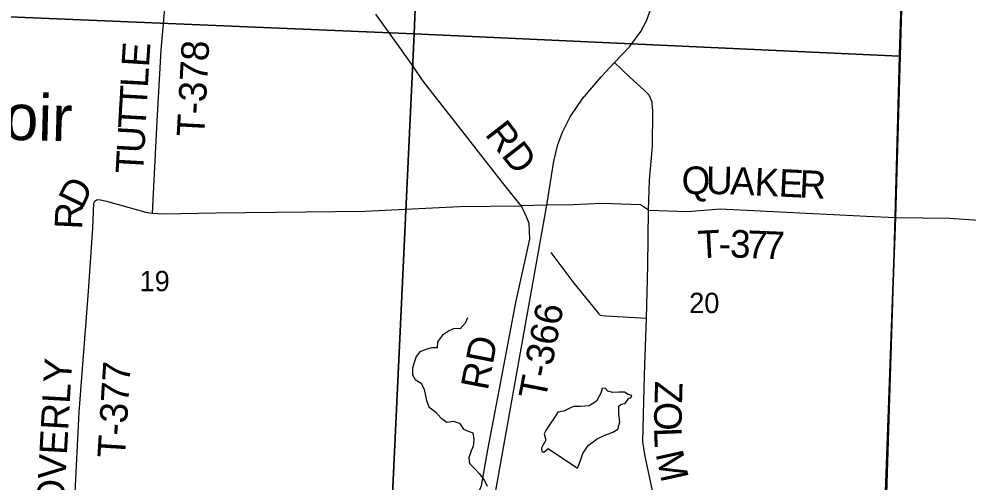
# Model space of a CAD drawing. Extents: x 1759416 to 2214760, y 252598 to 1116833.
# Drawn here: x 1948045 to 1958374, y 912773 to 917809 of the extents above; entities that cross this region are included whole.
import ezdxf

# ---------------------------------------------------------------- set-up
doc = ezdxf.new("R2010")
doc.units = 0
for name, color, linetype in [('GM_X_County_Road', 7, 'Continuous'), ('GM_X_County_Road_Text', 7, 'Continuous'), ('GM_X_Major_Lake_Text', 7, 'Continuous'), ('GM_X_Minor_Lake', 7, 'Continuous'), ('GM_X_Minor_River', 7, 'Continuous'), ('GM_X_Section', 7, 'Continuous'), ('GM_X_Section_Text', 7, 'Continuous'), ('GM_X_State_Route', 7, 'Continuous'), ('GM_X_Township', 7, 'Continuous'), ('GM_X_Township_Road', 7, 'Continuous'), ('GM_X_Township_Road_Text', 7, 'Continuous')]:
    doc.layers.add(name, color=color, linetype=linetype)

msp = doc.modelspace()

# ---------------------------------------------------------------- linework, layer by layer
at = {"layer": 'GM_X_County_Road'}
for points in [[(1953509, 915776), (1953318, 916014), (1952930, 916513), (1952445, 917134), (1952337, 917290), (1952198, 917489), (1951929, 917861)], [(1954937, 916894), (1954936, 916904), (1954903, 916980), (1954849, 917034), (1954695, 917171), (1954528, 917336)], [(1954978, 912496), (1954877, 912965), (1954855, 913071), (1954834, 913209), (1954852, 913937), (1954873, 914556), (1954889, 915125), (1954897, 915731), (1954907, 916057), (1954940, 916425), (1954944, 916807), (1954937, 916894)], [(1954897, 915731), (1954811, 915786), (1954390, 915801), (1954075, 915786), (1953791, 915785)], [(1953791, 915785), (1953509, 915776)]]:
    msp.add_lwpolyline(points, dxfattribs=at)
at = {"layer": 'GM_X_Minor_Lake'}
for points in [[(1954125, 912925), (1954151, 912995), (1954183, 913083), (1954241, 913170), (1954337, 913244), (1954415, 913278), (1954507, 913316), (1954561, 913346), (1954584, 913428), (1954574, 913512), (1954572, 913599), (1954598, 913619), (1954642, 913625), (1954684, 913683), (1954704, 913687), (1954716, 913715), (1954676, 913725), (1954636, 913749), (1954574, 913751), (1954508, 913747), (1954454, 913761), (1954424, 913793), (1954391, 913789), (1954377, 913739), (1954329, 913651), (1954249, 913601), (1954155, 913593), (1954079, 913595), (1954031, 913571), (1953975, 913545), (1953911, 913533), (1953873, 913476), (1953818, 913394), (1953778, 913332), (1953760, 913296), (1953780, 913228), (1953750, 913178), (1953730, 913140), (1953734, 913103), (1953758, 913099), (1953804, 913136)], [(1953804, 913136), (1954125, 912925)]]:
    msp.add_lwpolyline(points, dxfattribs=at)
at = {"layer": 'GM_X_Minor_River'}
msp.add_lwpolyline([(1952926, 914560), (1952900, 914501), (1952846, 914439), (1952782, 914441), (1952720, 914415), (1952653, 914369), (1952601, 914297), (1952597, 914233), (1952533, 914233), (1952471, 914213), (1952407, 914187), (1952369, 914137), (1952345, 914074), (1952329, 914010), (1952329, 913940), (1952357, 913888), (1952423, 913848), (1952453, 913778), (1952469, 913711), (1952479, 913659), (1952507, 913589), (1952577, 913537), (1952637, 913471), (1952703, 913424), (1952773, 913435), (1952839, 913414), (1952883, 913348), (1952933, 913324), (1952983, 913308), (1952997, 913236), (1952987, 913164), (1952965, 913112), (1952939, 913035), (1952949, 912973), (1953007, 912915), (1953055, 912865), (1953111, 912789), (1953141, 912728)], dxfattribs=at)
at = {"layer": 'GM_X_Section'}
for points in [[(1947099, 921072), (1952477, 920886), (1952344, 917647), (1946987, 917871)], [(1952477, 920886), (1953394, 920844), (1955546, 920745), (1957728, 920644), (1957626, 917421), (1957626, 917405), (1952344, 917647)], [(1952344, 917647), (1952087, 912177), (1946673, 912411), (1946987, 917871)], [(1952344, 917647), (1957626, 917405), (1957552, 914730), (1957469, 912061), (1957464, 911948), (1952087, 912177)]]:
    msp.add_lwpolyline(points, close=True, dxfattribs=at)
at = {"layer": 'GM_X_State_Route'}
for points in [[(1954198, 916965), (1954380, 917178), (1954528, 917336), (1954688, 917507), (1954814, 917674), (1954879, 917797), (1954965, 918053), (1955223, 919187)], [(1952216, 906771), (1952343, 907503), (1952586, 908815), (1952810, 910268), (1952866, 910610), (1953791, 915785), (1953865, 916262), (1953910, 916442), (1953960, 916579), (1954042, 916745), (1954128, 916868), (1954194, 916961), (1954198, 916965)]]:
    msp.add_lwpolyline(points, dxfattribs=at)
at = {"layer": 'GM_X_Township'}
for points in [[(1959158, 906479), (1957243, 906546), (1957347, 909188), (1957585, 915650), (1957760, 921682), (1957798, 922777), (1955985, 922511), (1955321, 922391), (1955313, 926444), (1955315, 926725), (1955324, 926909), (1955313, 928900), (1957476, 928914), (1959742, 928940)], [(1957760, 921682), (1957585, 915650), (1957347, 909188), (1957243, 906546), (1956080, 906593), (1955889, 906604), (1953807, 906686), (1952212, 906748), (1952068, 906753), (1947328, 906938), (1937425, 907470), (1932937, 907680), (1930733, 907844), (1930824, 909461), (1930891, 910644), (1931168, 914595), (1931473, 919044)]]:
    msp.add_lwpolyline(points, dxfattribs=at)
at = {"layer": 'GM_X_Township_Road'}
for points in [[(1949689, 918461), (1949648, 918135), (1949588, 917471), (1949546, 916699), (1949493, 915697)], [(1948640, 912299), (1948653, 912591), (1948701, 913534), (1948801, 914847), (1948849, 915534), (1948860, 915807), (1948870, 915829), (1948888, 915841), (1948914, 915845), (1948998, 915827), (1949427, 915707), (1949493, 915697), (1949619, 915689), (1950189, 915699), (1951809, 915720), (1952838, 915768), (1953509, 915776)], [(1953509, 915776), (1953566, 915662), (1953593, 915588), (1953601, 915414), (1953450, 914726), (1953269, 913769), (1953144, 913121), (1953075, 912732), (1953041, 912646)], [(1954897, 915731), (1955326, 915714), (1955678, 915744), (1957269, 915665)], [(1957269, 915665), (1957585, 915650), (1958174, 915642), (1959847, 915528)], [(1953833, 915268), (1954084, 914936), (1954336, 914622), (1954353, 914604)], [(1954353, 914604), (1954354, 914603), (1954369, 914588), (1954431, 914579), (1954873, 914556)]]:
    msp.add_lwpolyline(points, dxfattribs=at)

# ---------------------------------------------------------------- texts
at = {"layer": 'GM_X_County_Road_Text'}
for s, rotation, p in [('RD', 307.9619, (1953108, 916553)), ('Z', 268.4785, (1954968, 913872)), ('O', 268.5568, (1954962, 913647)), ('L', 272.1615, (1954956, 913362)), ('M', 282.4124, (1954972, 913080))]:
    msp.add_text(s, height=300, rotation=rotation, dxfattribs=at).set_placement(p)
at = {"layer": 'GM_X_Major_Lake_Text'}
msp.add_text('Reservoir', height=500, rotation=358.4735, dxfattribs=at).set_placement((1945761, 916553))
at = {"layer": 'GM_X_Section_Text'}
for s, p in [('19', (1949357, 914848)), ('20', (1955339, 914610))]:
    msp.add_text(s, height=221, rotation=0, dxfattribs=at).set_placement(p)
at = {"layer": 'GM_X_Township_Road_Text'}
for s, rotation, p in [('T-378', 86.9028, (1950060, 916521)), ('E', 86.2689, (1949459, 917280)), ('L', 86.8364, (1949447, 917057)), ('T', 86.8356, (1949435, 916833)), ('T', 86.8399, (1949422, 916609)), ('U', 86.8392, (1949408, 916345)), ('T', 86.8399, (1949395, 916121)), ('Q', 0.4299, (1955258, 915903)), ('U', 359.0893, (1955520, 915905)), ('A', 357.6644, (1955782, 915901)), ('K', 357.2778, (1956045, 915890)), ('E', 357.269, (1956309, 915878)), ('R', 357.2744, (1956533, 915867)), ('D', 64.2789, (1948734, 915732)), ('R', 87.3763, (1948731, 915517)), ('T', 3.1128, (1955440, 915204)), ('3', 358.548, (1955781, 915215)), ('7', 357.7096, (1955964, 915210)), ('7', 357.4908, (1956149, 915203)), ('-', 359.6019, (1955659, 915216)), ('T-366', 79.0098, (1953775, 913655)), ('RD', 79.0843, (1953146, 913760)), ('OVERLY', 86.7804, (1948533, 912485)), ('T-377', 86.4235, (1949197, 913027))]:
    msp.add_text(s, height=300, rotation=rotation, dxfattribs=at).set_placement(p)

doc.saveas('drawing.dxf')
